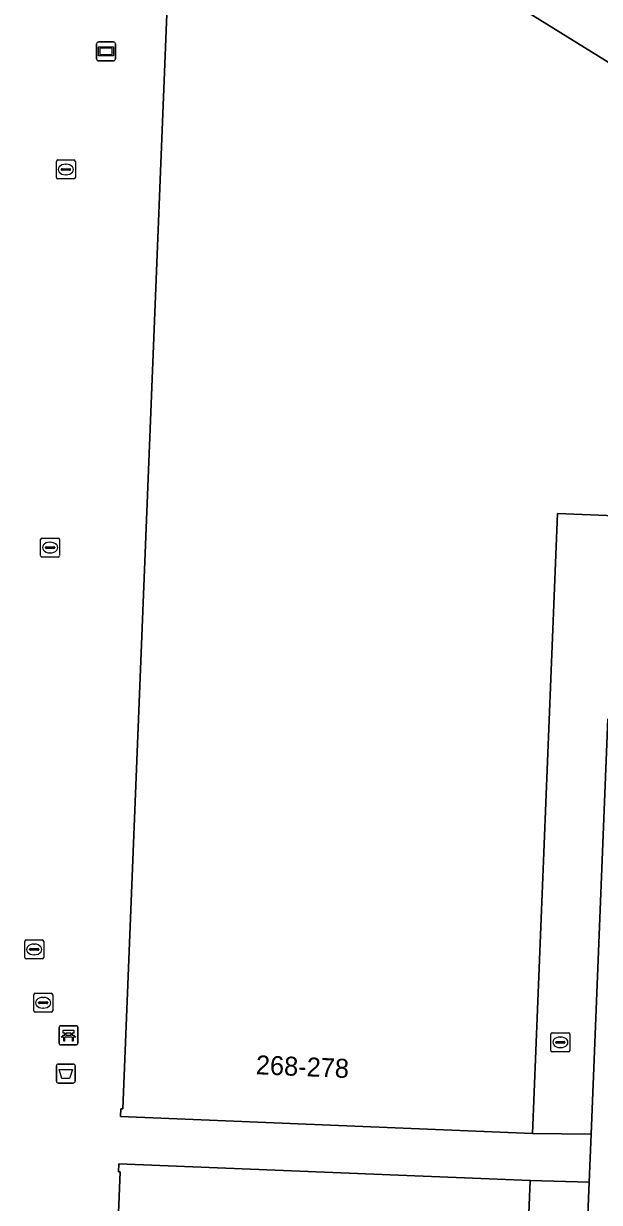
# Model space of a CAD drawing. Extents: x 160888 to 161385, y 386490 to 386908.
# Drawn here: x 161189.2 to 161219.5, y 386643.8 to 386705.9 of the extents above; entities that cross this region are included whole.
import ezdxf

# ---------------------------------------------------------------- set-up
doc = ezdxf.new("R2010")
doc.units = 0
for name, color, linetype in [('IMGEO_Afvalbak', 7, 'Continuous'), ('IMGEO_Bank', 7, 'Continuous'), ('IMGEO_Brandkraan', 7, 'Continuous'), ('IMGEO_Kolk', 7, 'Continuous'), ('IMGEO_Pand', 7, 'Continuous'), ('IMGEO_Pand_nummerreeks', 7, 'Continuous'), ('IMGEO_Reclamebord', 7, 'Continuous'), ('IMGEO_Rijbaan_lokaal_open', 7, 'Continuous'), ('IMGEO_Rioolput', 7, 'Continuous'), ('IMGEO_Voetgangersgebied_open', 7, 'Continuous'), ('IMGEO_Voetpad_open', 7, 'Continuous')]:
    doc.layers.add(name, color=color, linetype=linetype)

msp = doc.modelspace()

# ---------------------------------------------------------------- linework, layer by layer
at = {"layer": 'IMGEO_Afvalbak'}
for p, q in [((161190.919, 386650.214), (161190.919, 386651.014)), ((161190.919, 386651.014), (161190.919, 386650.214)), ((161191.019, 386651.114), (161191.809, 386651.114)), ((161191.809, 386651.114), (161191.019, 386651.114)), ((161191.909, 386651.014), (161191.909, 386650.214)), ((161191.909, 386650.214), (161191.909, 386651.014)), ((161191.809, 386650.114), (161191.019, 386650.114)), ((161191.019, 386650.114), (161191.809, 386650.114))]:
    msp.add_line(p, q, dxfattribs=at)
msp.add_lwpolyline([(161191.062, 386650.828), (161191.766, 386650.828), (161191.617, 386650.358), (161191.211, 386650.358), (161191.062, 386650.828)], dxfattribs=at)
for centre, start, end in [((161191.019, 386651.014), 90, 180), ((161191.019, 386651.014), 90, 180), ((161191.809, 386651.014), 0, 90), ((161191.809, 386651.014), 360, 90), ((161191.019, 386650.214), 180, 270), ((161191.019, 386650.214), 180, 270), ((161191.809, 386650.214), 270, 0), ((161191.809, 386650.214), 270, 0)]:
    msp.add_arc(centre, 0.1, start, end, dxfattribs=at)
at = {"layer": 'IMGEO_Bank'}
for p, q in [((161191.058, 386652.204), (161191.058, 386653.045)), ((161191.058, 386653.045), (161191.058, 386652.204)), ((161191.133, 386653.129), (161191.974, 386653.129)), ((161191.974, 386653.129), (161191.133, 386653.129)), ((161191.367, 386652.635), (161191.367, 386652.741)), ((161191.411, 386652.741), (161191.411, 386652.635)), ((161191.699, 386652.747), (161191.417, 386652.747)), ((161191.417, 386652.629), (161191.699, 386652.629)), ((161191.705, 386652.635), (161191.705, 386652.741)), ((161191.749, 386652.741), (161191.749, 386652.635)), ((161192.058, 386653.054), (161192.058, 386652.213)), ((161192.058, 386652.213), (161192.058, 386653.054)), ((161191.983, 386652.129), (161191.142, 386652.129)), ((161191.142, 386652.129), (161191.983, 386652.129)), ((161191.755, 386652.527), (161191.362, 386652.527))]:
    msp.add_line(p, q, dxfattribs=at)
for points in [[(161191.305, 386652.527), (161191.163, 386652.527), (161191.275, 386652.629), (161191.361, 386652.629)], [(161191.361, 386652.747), (161191.275, 386652.747), (161191.275, 386652.908), (161191.838, 386652.908), (161191.838, 386652.747), (161191.755, 386652.747)], [(161191.755, 386652.629), (161191.838, 386652.629), (161191.95, 386652.527), (161191.811, 386652.527)], [(161191.355, 386652.52), (161191.355, 386652.313), (161191.312, 386652.313), (161191.312, 386652.52)], [(161191.805, 386652.52), (161191.805, 386652.313), (161191.761, 386652.313), (161191.761, 386652.52)]]:
    msp.add_lwpolyline(points, dxfattribs=at)
for centre, radius, start, end in [((161191.136, 386653.051), 0.0779, 92.4484, 184.28452), ((161191.136, 386653.051), 0.0779, 92.4484, 184.28452), ((161191.36, 386652.74), 0.00671, 2.89567, 87.10433), ((161191.36, 386652.636), 0.00671, 272.89567, 357.10433), ((161191.417, 386652.74), 0.00671, 92.89567, 177.10433), ((161191.417, 386652.636), 0.00671, 182.89567, 267.10433), ((161191.699, 386652.74), 0.00671, 2.89567, 87.10433), ((161191.699, 386652.636), 0.00671, 272.89567, 357.10433), ((161191.756, 386652.74), 0.00671, 92.89567, 177.10433), ((161191.756, 386652.636), 0.00671, 182.89567, 267.10433), ((161191.98, 386653.051), 0.0779, 2.4484, 94.28452), ((161191.98, 386653.051), 0.0779, 2.4484, 94.28452), ((161191.136, 386652.207), 0.0779, 182.4484, 274.28452), ((161191.136, 386652.207), 0.0779, 182.4484, 274.28452), ((161191.305, 386652.52), 0.00671, 2.89567, 87.10433), ((161191.362, 386652.52), 0.00671, 92.89567, 177.10433), ((161191.754, 386652.52), 0.00671, 2.89567, 87.10433), ((161191.811, 386652.52), 0.00671, 92.89567, 177.10433), ((161191.98, 386652.207), 0.0779, 272.4484, 4.28452), ((161191.98, 386652.207), 0.0779, 272.4484, 4.28452)]:
    msp.add_arc(centre, radius, start, end, dxfattribs=at)
at = {"layer": 'IMGEO_Brandkraan'}
for p, q in [((161216.976, 386651.833), (161216.976, 386652.685)), ((161217.051, 386652.759), (161217.903, 386652.759)), ((161217.977, 386652.685), (161217.977, 386651.833)), ((161217.235, 386652.253), (161217.235, 386652.265)), ((161217.673, 386652.216), (161217.275, 386652.216)), ((161217.278, 386652.302), (161217.676, 386652.302)), ((161217.487, 386651.979), (161217.462, 386651.979)), ((161217.464, 386652.539), (161217.489, 386652.539)), ((161217.719, 386652.265), (161217.719, 386652.253)), ((161217.903, 386651.759), (161217.051, 386651.759))]:
    msp.add_line(p, q, dxfattribs=at)
for points in [[(161216.976, 386651.833), (161216.976, 386652.685)], [(161217.051, 386652.759), (161217.903, 386652.759)], [(161217.977, 386652.685), (161217.977, 386651.833)], [(161217.903, 386651.759), (161217.051, 386651.759)]]:
    msp.add_lwpolyline(points, dxfattribs=at)
for centre, radius, start, end in [((161217.053, 386652.683), 0.0765, 91.55205, 178.44795), ((161217.053, 386652.683), 0.0765, 91.55205, 178.44795), ((161217.901, 386652.683), 0.0765, 1.55205, 88.44795), ((161217.901, 386652.683), 0.0765, 1.55205, 88.44795), ((161217.275, 386652.262), 0.0403, 85.87752, 175.75265), ((161217.272, 386652.252), 0.0366, 178.93798, 274.71019), ((161217.676, 386652.259), 0.043, 264.86636, 352.45326), ((161217.68, 386652.264), 0.0386, 1.73085, 96.63898), ((161217.053, 386651.835), 0.0765, 181.55205, 268.44795), ((161217.053, 386651.835), 0.0765, 181.55205, 268.44795), ((161217.901, 386651.835), 0.0765, 271.55205, 358.44795), ((161217.901, 386651.835), 0.0765, 271.55205, 358.44795)]:
    msp.add_arc(centre, radius, start, end, dxfattribs=at)
for centre, major_axis, ratio, start_param, end_param in [((161217.463, 386652.259), (-0.387, 0.002), 0.722429, 4.712389, 7.853982), ((161217.488, 386652.259), (-0.39, 0.002), 0.717154, 1.570796, 4.712389)]:
    msp.add_ellipse(centre, major_axis=major_axis, ratio=ratio, start_param=start_param, end_param=end_param, dxfattribs=at)
at = {"layer": 'IMGEO_Kolk'}
for p, q in [((161190.918, 386697.83), (161190.918, 386698.682)), ((161190.993, 386698.756), (161191.845, 386698.756)), ((161191.919, 386698.682), (161191.919, 386697.83)), ((161191.177, 386698.25), (161191.177, 386698.262)), ((161191.615, 386698.213), (161191.217, 386698.213)), ((161191.22, 386698.299), (161191.618, 386698.299)), ((161191.429, 386697.976), (161191.404, 386697.976)), ((161191.406, 386698.536), (161191.431, 386698.536)), ((161191.661, 386698.262), (161191.661, 386698.25)), ((161191.845, 386697.756), (161190.993, 386697.756)), ((161190.087, 386677.905), (161190.087, 386678.757)), ((161190.162, 386678.831), (161191.014, 386678.831)), ((161191.088, 386678.757), (161191.088, 386677.905)), ((161190.346, 386678.325), (161190.346, 386678.337)), ((161190.784, 386678.288), (161190.386, 386678.288)), ((161190.389, 386678.374), (161190.787, 386678.374)), ((161190.575, 386678.611), (161190.6, 386678.611)), ((161190.83, 386678.337), (161190.83, 386678.325)), ((161191.014, 386677.831), (161190.162, 386677.831)), ((161190.598, 386678.051), (161190.573, 386678.051)), ((161189.25, 386656.728), (161189.25, 386657.58)), ((161189.325, 386657.654), (161190.177, 386657.654)), ((161190.251, 386657.58), (161190.251, 386656.728)), ((161189.509, 386657.148), (161189.509, 386657.16)), ((161189.947, 386657.111), (161189.549, 386657.111)), ((161189.552, 386657.197), (161189.95, 386657.197)), ((161189.738, 386657.434), (161189.763, 386657.434)), ((161189.993, 386657.16), (161189.993, 386657.148)), ((161190.177, 386656.654), (161189.325, 386656.654)), ((161189.761, 386656.874), (161189.736, 386656.874))]:
    msp.add_line(p, q, dxfattribs=at)
for points in [[(161190.918, 386697.83), (161190.918, 386698.682)], [(161190.993, 386698.756), (161191.845, 386698.756)], [(161191.919, 386698.682), (161191.919, 386697.83)], [(161191.845, 386697.756), (161190.993, 386697.756)], [(161190.087, 386677.905), (161190.087, 386678.757)], [(161190.162, 386678.831), (161191.014, 386678.831)], [(161191.088, 386678.757), (161191.088, 386677.905)], [(161191.014, 386677.831), (161190.162, 386677.831)], [(161189.25, 386656.728), (161189.25, 386657.58)], [(161189.325, 386657.654), (161190.177, 386657.654)], [(161190.251, 386657.58), (161190.251, 386656.728)], [(161190.177, 386656.654), (161189.325, 386656.654)]]:
    msp.add_lwpolyline(points, dxfattribs=at)
for centre, radius, start, end in [((161190.995, 386698.68), 0.0765, 91.55205, 178.44795), ((161190.995, 386698.68), 0.0765, 91.55205, 178.44795), ((161191.843, 386698.68), 0.0765, 1.55205, 88.44795), ((161191.843, 386698.68), 0.0765, 1.55205, 88.44795), ((161191.217, 386698.259), 0.0403, 85.87752, 175.75265), ((161191.214, 386698.249), 0.0366, 178.93798, 274.71019), ((161191.618, 386698.256), 0.043, 264.86636, 352.45326), ((161191.622, 386698.261), 0.0386, 1.73085, 96.63898), ((161190.995, 386697.832), 0.0765, 181.55205, 268.44795), ((161190.995, 386697.832), 0.0765, 181.55205, 268.44795), ((161191.843, 386697.832), 0.0765, 271.55205, 358.44795), ((161191.843, 386697.832), 0.0765, 271.55205, 358.44795), ((161190.164, 386678.755), 0.0765, 91.55205, 178.44795), ((161190.164, 386678.755), 0.0765, 91.55205, 178.44795), ((161191.012, 386678.755), 0.0765, 1.55205, 88.44795), ((161191.012, 386678.755), 0.0765, 1.55205, 88.44795), ((161190.386, 386678.334), 0.0403, 85.87752, 175.75265), ((161190.383, 386678.324), 0.0366, 178.93798, 274.71019), ((161190.787, 386678.331), 0.043, 264.86636, 352.45326), ((161190.791, 386678.336), 0.0386, 1.73085, 96.63898), ((161190.164, 386677.907), 0.0765, 181.55205, 268.44795), ((161190.164, 386677.907), 0.0765, 181.55205, 268.44795), ((161191.012, 386677.907), 0.0765, 271.55205, 358.44795), ((161191.012, 386677.907), 0.0765, 271.55205, 358.44795), ((161189.327, 386657.578), 0.0765, 91.55205, 178.44795), ((161189.327, 386657.578), 0.0765, 91.55205, 178.44795), ((161190.175, 386657.578), 0.0765, 1.55205, 88.44795), ((161190.175, 386657.578), 0.0765, 1.55205, 88.44795), ((161189.549, 386657.157), 0.0403, 85.87752, 175.75265), ((161189.546, 386657.147), 0.0366, 178.93798, 274.71019), ((161189.95, 386657.154), 0.043, 264.86636, 352.45326), ((161189.954, 386657.159), 0.0386, 1.73085, 96.63898), ((161189.327, 386656.73), 0.0765, 181.55205, 268.44795), ((161189.327, 386656.73), 0.0765, 181.55205, 268.44795), ((161190.175, 386656.73), 0.0765, 271.55205, 358.44795), ((161190.175, 386656.73), 0.0765, 271.55205, 358.44795)]:
    msp.add_arc(centre, radius, start, end, dxfattribs=at)
for centre, major_axis, ratio, start_param, end_param in [((161191.405, 386698.256), (-0.387, 0.002), 0.722429, 4.712389, 7.853982), ((161191.43, 386698.256), (-0.39, 0.002), 0.717154, 1.570796, 4.712389), ((161190.574, 386678.331), (-0.387, 0.002), 0.722429, 4.712389, 7.853982), ((161190.599, 386678.331), (-0.39, 0.002), 0.717154, 1.570796, 4.712389), ((161189.737, 386657.154), (-0.387, 0.002), 0.722429, 4.712389, 7.853982), ((161189.762, 386657.154), (-0.39, 0.002), 0.717154, 1.570796, 4.712389)]:
    msp.add_ellipse(centre, major_axis=major_axis, ratio=ratio, start_param=start_param, end_param=end_param, dxfattribs=at)
at = {"layer": 'IMGEO_Pand'}
for points in [[(161234.482, 386694.929), (161214.777, 386707.152), (161205, 386707.543), (161204.996, 386707.443), (161196.801, 386707.775), (161194.42, 386648.752), (161194.32, 386648.757), (161194.302, 386648.347), (161216.005, 386647.458), (161217.32, 386680.124), (161234.274, 386679.434), (161234.896, 386694.91)], [(161194.188, 386645.434), (161194.288, 386645.43), (161192.672, 386605.589), (161192.572, 386605.592), (161192.56, 386605.179), (161214.242, 386604.304), (161215.889, 386644.972), (161194.205, 386645.849)]]:
    msp.add_lwpolyline(points, close=True, dxfattribs=at)
at = {"layer": 'IMGEO_Reclamebord'}
for p, q in [((161193.037, 386704.08), (161193.037, 386704.88)), ((161193.037, 386704.88), (161193.037, 386704.08)), ((161193.137, 386704.98), (161193.927, 386704.98)), ((161193.927, 386704.98), (161193.137, 386704.98)), ((161194.027, 386704.88), (161194.027, 386704.08)), ((161194.027, 386704.08), (161194.027, 386704.88)), ((161193.927, 386703.98), (161193.137, 386703.98)), ((161193.137, 386703.98), (161193.927, 386703.98))]:
    msp.add_line(p, q, dxfattribs=at)
for points in [[(161193.138, 386704.712), (161193.926, 386704.712), (161193.926, 386704.248), (161193.138, 386704.248), (161193.138, 386704.712)], [(161193.203, 386704.647), (161193.203, 386704.313), (161193.861, 386704.313), (161193.861, 386704.647), (161193.203, 386704.647)]]:
    msp.add_lwpolyline(points, dxfattribs=at)
for centre, start, end in [((161193.137, 386704.88), 90, 180), ((161193.137, 386704.88), 90, 180), ((161193.927, 386704.88), 0, 90), ((161193.927, 386704.88), 360, 90), ((161193.137, 386704.08), 180, 270), ((161193.137, 386704.08), 180, 270), ((161193.927, 386704.08), 270, 0), ((161193.927, 386704.08), 270, 0)]:
    msp.add_arc(centre, 0.1, start, end, dxfattribs=at)
at = {"layer": 'IMGEO_Rijbaan_lokaal_open'}
msp.add_lwpolyline([(161219.977, 386669.302), (161219.091, 386647.411), (161218.989, 386644.89), (161217.342, 386604.22), (161217.24, 386601.701), (161217.156, 386599.626)], dxfattribs=at)
at = {"layer": 'IMGEO_Rioolput'}
for p, q in [((161189.724, 386653.917), (161189.724, 386654.769)), ((161189.799, 386654.843), (161190.651, 386654.843)), ((161190.212, 386654.623), (161190.237, 386654.623)), ((161190.725, 386654.769), (161190.725, 386653.917)), ((161190.651, 386653.843), (161189.799, 386653.843)), ((161189.983, 386654.337), (161189.983, 386654.349)), ((161190.421, 386654.3), (161190.023, 386654.3)), ((161190.026, 386654.386), (161190.424, 386654.386)), ((161190.235, 386654.063), (161190.21, 386654.063)), ((161190.467, 386654.349), (161190.467, 386654.337))]:
    msp.add_line(p, q, dxfattribs=at)
for points in [[(161189.724, 386653.917), (161189.724, 386654.769)], [(161189.799, 386654.843), (161190.651, 386654.843)], [(161190.725, 386654.769), (161190.725, 386653.917)], [(161190.651, 386653.843), (161189.799, 386653.843)]]:
    msp.add_lwpolyline(points, dxfattribs=at)
for centre, radius, start, end in [((161189.801, 386654.767), 0.0765, 91.55205, 178.44795), ((161189.801, 386654.767), 0.0765, 91.55205, 178.44795), ((161190.649, 386654.767), 0.0765, 1.55205, 88.44795), ((161190.649, 386654.767), 0.0765, 1.55205, 88.44795), ((161189.801, 386653.919), 0.0765, 181.55205, 268.44795), ((161189.801, 386653.919), 0.0765, 181.55205, 268.44795), ((161190.023, 386654.346), 0.0403, 85.87752, 175.75265), ((161190.02, 386654.336), 0.0366, 178.93798, 274.71019), ((161190.424, 386654.343), 0.043, 264.86636, 352.45326), ((161190.428, 386654.348), 0.0386, 1.73085, 96.63898), ((161190.649, 386653.919), 0.0765, 271.55205, 358.44795), ((161190.649, 386653.919), 0.0765, 271.55205, 358.44795)]:
    msp.add_arc(centre, radius, start, end, dxfattribs=at)
for centre, major_axis, ratio, start_param, end_param in [((161190.211, 386654.343), (-0.387, 0.002), 0.722429, 4.712389, 7.853982), ((161190.236, 386654.343), (-0.39, 0.002), 0.717154, 1.570796, 4.712389)]:
    msp.add_ellipse(centre, major_axis=major_axis, ratio=ratio, start_param=start_param, end_param=end_param, dxfattribs=at)
at = {"layer": 'IMGEO_Voetgangersgebied_open'}
for points in [[(161267.035, 386750.03), (161265.767, 386750.053), (161265.005, 386750.043), (161218.231, 386752.088), (161189.757, 386753.134), (161187.146, 386761.187), (161186.852, 386753.913), (161186.694, 386750), (161186.656, 386749.048), (161186.65, 386748.905), (161236.989, 386746.871), (161236.376, 386731.786), (161235.961, 386731.803), (161215.329, 386721.218), (161215.194, 386719.154), (161214.868, 386709.114), (161214.777, 386707.152), (161234.482, 386694.929), (161234.896, 386694.91), (161234.274, 386679.434), (161217.32, 386680.124), (161216.005, 386647.458), (161219.091, 386647.411), (161219.977, 386669.302)], [(161191.198, 386569.006), (161192.541, 386602.265), (161192.441, 386602.269), (161192.456, 386602.678), (161214.141, 386601.806), (161217.24, 386601.701), (161217.342, 386604.22), (161214.242, 386604.304), (161192.56, 386605.179), (161192.572, 386605.592), (161192.672, 386605.589), (161194.288, 386645.43), (161194.188, 386645.434), (161194.205, 386645.849), (161215.889, 386644.972), (161218.989, 386644.89), (161219.091, 386647.411), (161216.005, 386647.458), (161194.302, 386648.347), (161194.32, 386648.757), (161194.42, 386648.752), (161196.801, 386707.775)]]:
    msp.add_lwpolyline(points, dxfattribs=at)
at = {"layer": 'IMGEO_Voetpad_open'}
msp.add_lwpolyline([(161214.242, 386604.304), (161217.342, 386604.22), (161218.989, 386644.89), (161215.889, 386644.972)], close=True, dxfattribs=at)

# ---------------------------------------------------------------- texts
at = {"layer": 'IMGEO_Pand_nummerreeks'}
msp.add_text('268-278', height=1, rotation=357.65436, dxfattribs=at).set_placement((161201.414, 386650.578))

doc.saveas('drawing.dxf')
